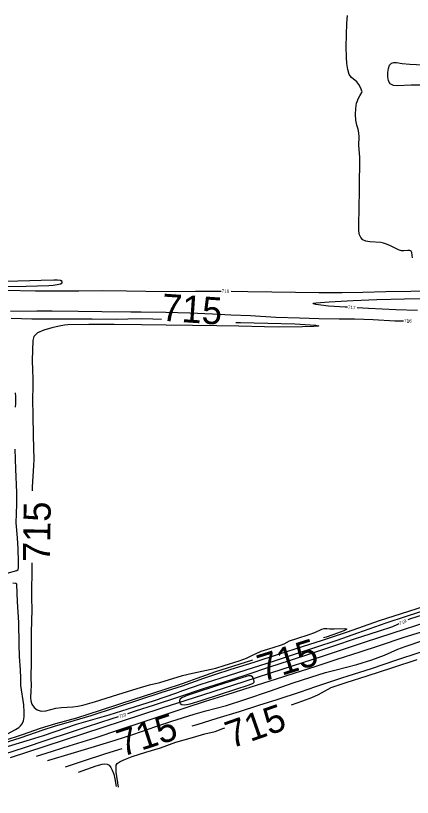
# Model space of a CAD drawing. Extents: x -468563856 to 36492962, y -306094093 to 11899197.
# Drawn here: x 1820050 to 1820533, y 530391 to 531343 of the extents above; entities that cross this region are included whole.
import ezdxf

# ---------------------------------------------------------------- set-up
doc = ezdxf.new("R2010")
doc.units = 0
for name, color, linetype in [('DT_X_Contour_Minor', 7, 'Continuous'), ('Level 14', 7, 'Continuous'), ('Level 19', 7, 'Continuous')]:
    doc.layers.add(name, color=color, linetype=linetype)

msp = doc.modelspace()

# ---------------------------------------------------------------- linework, layer by layer
at = {"layer": 'DT_X_Contour_Minor'}
for points in [[(1820466.33, 531239.8), (1820467.1, 531242.15), (1820469.18, 531245.91), (1820471.87, 531249.69), (1820471.98, 531250.79), (1820470.08, 531255.7), (1820468.15, 531259.47), (1820465.56, 531262.92), (1820459.18, 531267.98), (1820456.4, 531271.79), (1820454.53, 531277.77), (1820453.44, 531285.12), (1820452.87, 531292.66), (1820452.58, 531305.86), (1820452.86, 531319.49), (1820453.6, 531334.34), (1820454.38, 531343.39)], [(1820554.3, 531258.8), (1820531.6, 531258.86), (1820515.27, 531258.02), (1820510.24, 531258.39), (1820506.37, 531260.2), (1820504.16, 531263.92), (1820503.35, 531268.9), (1820503.48, 531274.25), (1820504.2, 531279.12), (1820505.55, 531283.02), (1820507.66, 531285.55), (1820510.58, 531286.46), (1820513.97, 531286.25), (1820520.75, 531285.01), (1820530.32, 531284.19), (1820554.56, 531283.23)], [(1820533.31, 531048.28), (1820532.58, 531054.96), (1820531.75, 531056.64), (1820530.07, 531057.29), (1820527.78, 531057.27), (1820522.81, 531056.83), (1820520.03, 531057.16), (1820516.43, 531058.3), (1820506.6, 531062.92), (1820501.83, 531065.14), (1820498, 531066.51), (1820494.61, 531067.16), (1820481.28, 531067.92), (1820476.67, 531068.81), (1820473.04, 531070.48), (1820470.45, 531073.06), (1820468.82, 531076.58), (1820468.04, 531081.03), (1820467.84, 531086.05), (1820468.39, 531111.42), (1820468.79, 531128.59), (1820468.97, 531144.22), (1820469.33, 531159.11), (1820469.04, 531170.5), (1820468.05, 531185.76), (1820468.36, 531195.83), (1820468.06, 531200.67), (1820467.01, 531205.3), (1820465.6, 531210.18), (1820464.41, 531215.91), (1820463.89, 531222.82), (1820464.17, 531230.15), (1820465.27, 531236.87), (1820466.33, 531239.8)], [(1819858.47, 531016.5), (1819874.25, 531016.03), (1819901.63, 531015.56), (1819930.13, 531015), (1819963.03, 531014.01), (1819983.8, 531013.7), (1820018.21, 531013.65), (1820033.98, 531013.43), (1820062.78, 531014.12), (1820090.66, 531014.82), (1820095.79, 531015.2), (1820100.88, 531015.85), (1820104.86, 531016.84), (1820106.85, 531018.19), (1820106.8, 531019.62), (1820104.83, 531020.75), (1820101.19, 531021.33), (1820096.45, 531021.45), (1820081.35, 531020.88), (1820067.45, 531020.45), (1820038.31, 531019.53), (1820029.69, 531019.43)], [(1819643.06, 531014.48), (1819666.9, 531014.02), (1819695.98, 531013.52), (1819721.13, 531013.2), (1819750.34, 531012.81), (1819784.04, 531012.39), (1819810.69, 531011.89), (1819838.93, 531011.3), (1819869.9, 531011.21), (1819907.1, 531010.74), (1819937.02, 531010.46), (1819972.82, 531010.14), (1820003.71, 531009.72), (1820037.35, 531009.26), (1820074.26, 531008.3), (1820093.49, 531008.12), (1820127.08, 531008.25), (1820155.77, 531008.64), (1820184.94, 531008.41), (1820208.61, 531007.92), (1820244.29, 531007.51), (1820269.27, 531007.68), (1820300.38, 531007.87)], [(1820312.38, 531007.74), (1820332.78, 531007.37), (1820362.21, 531006.96), (1820390.83, 531006.48), (1820419.24, 531006.26), (1820447.84, 531006.31), (1820473.03, 531006.54), (1820500.98, 531007.32), (1820531.19, 531007.79), (1820554.4, 531008.3)], [(1820454.05, 530988.41), (1820451.44, 530988.56), (1820431.13, 530989.76), (1820415.68, 530991.78), (1820412.63, 530992.4), (1820412.41, 530993.07), (1820416.2, 530993.75), (1820432.03, 530995.05), (1820460.99, 530996.51), (1820490.08, 530997.63), (1820523.7, 530998.33), (1820549.42, 530998.81)], [(1820043.94, 530983.51), (1820075.99, 530983.99), (1820094.66, 530984.05), (1820126.32, 530983.58), (1820155.05, 530983.13), (1820190.22, 530982.64), (1820203.03, 530982.87), (1820232.85, 530982.34), (1820262.3, 530981.56), (1820289.73, 530980.3), (1820312.09, 530978.99), (1820336.08, 530978.39), (1820367.11, 530976.37), (1820395.88, 530975.42), (1820419.48, 530974.78), (1820444.13, 530974.34), (1820462.94, 530974.06), (1820485.5, 530973.22), (1820511.86, 530971.77), (1820522.53, 530971.73)], [(1820539.43, 530984.19), (1820513.21, 530985.33), (1820479.62, 530986.93), (1820466.03, 530987.72)], [(1820044.52, 530975.05), (1820069.74, 530974.32), (1820084.28, 530974.13), (1820114.28, 530974.23), (1820143.33, 530974.12), (1820172.73, 530973.92), (1820186.8, 530974), (1820203.68, 530974.57), (1820217.01, 530974.16), (1820227.93, 530973.82)], [(1820318.43, 530969.89), (1820324.02, 530969.67), (1820357.17, 530968.78), (1820389.93, 530967.99), (1820396.72, 530967.78), (1820408.88, 530966.95), (1820415.48, 530966.3), (1820419.2, 530965.64), (1820418.17, 530965.09), (1820413.41, 530964.67), (1820399.27, 530964.26), (1820370.55, 530964.11), (1820353.32, 530964.33), (1820321.99, 530965.19), (1820295.17, 530965.67), (1820265.45, 530965.94), (1820233.53, 530966.29), (1820203.5, 530966.75), (1820170.08, 530967.25), (1820139.21, 530967.09), (1820113.68, 530966.81), (1820109.49, 530966.36), (1820103.06, 530965.26), (1820094.09, 530963.3), (1820084.48, 530960.5), (1820076.67, 530956.95), (1820072.45, 530952.76), (1820070.98, 530947.94), (1820070.26, 530923.79), (1820070.68, 530911.4), (1820071.14, 530901.56), (1820071.11, 530892.82), (1820070.63, 530875.01), (1820070.94, 530857.2), (1820071.3, 530831.7), (1820072.23, 530802.98), (1820072.03, 530795.68), (1820070.37, 530769.1), (1820070.26, 530764.75)], [(1820050.08, 530866.43), (1820050.46, 530870.63), (1820050.46, 530879.72), (1820050.11, 530884.08)], [(1820039.71, 530664.59), (1820051.51, 530667.67), (1820053.24, 530668.91), (1820053.62, 530670.84), (1820053.64, 530678.16), (1820053.21, 530694), (1820052.22, 530707.51), (1820050.58, 530725.96), (1820051.54, 530748.62), (1820051.5, 530762.64), (1820050.55, 530790.91), (1820049.53, 530815.45)], [(1820975, 530749.89), (1820974.39, 530749.69), (1820955.82, 530743.7), (1820926.89, 530734.79), (1820898.46, 530725.6), (1820872.39, 530717.07), (1820843.48, 530707.6), (1820815.52, 530698.58), (1820788.91, 530689.89), (1820759.92, 530680.44), (1820733.01, 530671.94), (1820706.96, 530663.61), (1820679.3, 530654.6), (1820651.55, 530645.41), (1820642.4, 530642.94), (1820632.42, 530641.65), (1820626.79, 530640.14), (1820605.78, 530633.36), (1820576.19, 530623.56), (1820546.48, 530613.85), (1820531, 530608.69), (1820527.63, 530607.45)], [(1820069.85, 530677.14), (1820070, 530673.23), (1820069.76, 530663.22), (1820069.24, 530646.18), (1820069.37, 530634.36), (1820069.8, 530619.63), (1820068.94, 530592.7), (1820068.87, 530567.51), (1820069.1, 530557.47), (1820068.61, 530536.58), (1820069.02, 530528.17), (1820068.67, 530520.75), (1820068.15, 530513.02), (1820068.5, 530508.93), (1820069.87, 530504.87), (1820072.6, 530501.08), (1820076.53, 530498.12), (1820081.31, 530496.62), (1820086.7, 530496.96), (1820099.12, 530499.93), (1820106.08, 530500.79), (1820119.82, 530501.63), (1820125.89, 530502.48), (1820131.85, 530503.82), (1820146.05, 530507.95), (1820174.76, 530516.68), (1820198.17, 530524.08), (1820212.95, 530528.32), (1820225.55, 530531.53), (1820253.4, 530539.82), (1820265.44, 530542.72), (1820293.72, 530548.93), (1820303.85, 530551.94), (1820322.28, 530557.8), (1820331.25, 530561.07), (1820337.8, 530564.03), (1820343.13, 530566.75), (1820349.13, 530569.41), (1820357.03, 530572.12), (1820372.65, 530576.89), (1820377, 530578.52), (1820383.67, 530581.88), (1820392.71, 530584.95), (1820407.56, 530589.78), (1820414.47, 530592.31), (1820423.01, 530596.2), (1820425.88, 530597.08), (1820428.87, 530597.11), (1820432.69, 530596.71), (1820438.02, 530596.48), (1820451, 530597), (1820453.29, 530596.37), (1820449.83, 530594.38), (1820436.21, 530589.26), (1820428.07, 530586.52), (1820425.07, 530585.59)], [(1820040.2, 530468.81), (1820050.15, 530474.11), (1820053.97, 530476.63), (1820056.02, 530478.38), (1820058, 530480.9), (1820059.52, 530484.58), (1820060.31, 530489.55), (1820060.49, 530495.06), (1820059.93, 530504.12), (1820056.64, 530527.55), (1820056.36, 530536.77), (1820055.97, 530546.62), (1820054.88, 530563), (1820054.54, 530578.08), (1820054.03, 530604.41), (1820052.28, 530629.38), (1820051.43, 530651.11), (1820050.18, 530651.82), (1820046.88, 530652.48)], [(1820739.43, 530632.78), (1820718.62, 530626.11), (1820701.76, 530620.43), (1820674.7, 530611.84), (1820659.02, 530606.82), (1820627.65, 530596.01), (1820609.42, 530589.65), (1820580.36, 530579.93), (1820572.52, 530577.51), (1820541.13, 530567.28), (1820513.91, 530558.43), (1820483.19, 530548.12), (1820454.82, 530539.23), (1820446.73, 530536.65), (1820415.19, 530525.87), (1820396.62, 530519.72), (1820368.26, 530510.3), (1820345.95, 530503.3), (1820322.25, 530495.81), (1820295.29, 530487.44), (1820270.81, 530479.96), (1820264.78, 530478.05)], [(1820547.68, 530624.01), (1820519.59, 530615.03), (1820492.74, 530606.26), (1820473.23, 530599.58), (1820453.65, 530592.62), (1820423.53, 530582.32), (1820399.03, 530574.64), (1820371, 530565.67), (1820340.36, 530555.79), (1820311.99, 530546.98), (1820292.09, 530540.8), (1820278.77, 530536.16), (1820253.04, 530526.96), (1820227.11, 530518.62), (1820200.89, 530510.08), (1820171.24, 530500.36), (1820141.58, 530490.7), (1820120.93, 530484.56), (1820097.09, 530477.71), (1820084.29, 530473.61), (1820055.03, 530463.63), (1820023.65, 530453.82)], [(1820035.98, 530452.21), (1820073.33, 530463.49), (1820083.87, 530466.96), (1820111.34, 530476.3), (1820124.26, 530480.39), (1820152.76, 530488.63), (1820163.98, 530491.81), (1820187.22, 530499.21), (1820219.08, 530509.55), (1820245.27, 530518.29), (1820253.76, 530521.67), (1820275.93, 530529.38), (1820299.09, 530536.64), (1820330.8, 530546.64), (1820364.03, 530557.42), (1820391.03, 530566.34), (1820414.28, 530573.87), (1820441.5, 530582.79), (1820466.76, 530591.9), (1820501.45, 530604.04), (1820526.16, 530612.23), (1820552.63, 530620.56)], [(1820075.51, 530441.43), (1820087.42, 530445.4), (1820115.34, 530454.39), (1820146.83, 530464.12), (1820177.17, 530473.97), (1820205.38, 530483.31), (1820232.14, 530492.46), (1820257.81, 530501.03), (1820281.44, 530508.58), (1820307.79, 530516.82), (1820336.91, 530525.99), (1820366.57, 530535.4), (1820389.44, 530542.78), (1820416.12, 530551.36), (1820441.62, 530559.58), (1820469.44, 530568.53), (1820493.22, 530576.28), (1820523.05, 530586.42), (1820542.91, 530592.65), (1820572.16, 530601.61), (1820581.7, 530604.81)], [(1820516.59, 530602.75), (1820515.14, 530602.09), (1820508.9, 530599.3), (1820491.69, 530593.62), (1820462.44, 530583.96), (1820438.2, 530575.84), (1820409.18, 530566.13), (1820384.33, 530557.96), (1820358.04, 530549.4), (1820331.71, 530540.81), (1820301.66, 530530.98), (1820277.33, 530523.08), (1820248.36, 530513.65), (1820217.47, 530503.38), (1820197.08, 530496.63), (1820186.48, 530493.18)], [(1820089.02, 530436.34), (1820090.52, 530436.81), (1820117.62, 530444.67), (1820142.09, 530452.12), (1820171.19, 530461.12), (1820192.97, 530468.15), (1820221.02, 530477.77), (1820240.51, 530484.21), (1820267.67, 530492.78), (1820281.61, 530496.65), (1820306.77, 530503.32), (1820329.04, 530510.66), (1820360.26, 530521.18), (1820386.97, 530530.45), (1820409.47, 530537.72), (1820427.5, 530543.42), (1820440.44, 530546.79), (1820465.59, 530553.3), (1820483.73, 530558.82), (1820491.63, 530561.61), (1820499.12, 530564.69), (1820515.54, 530572.04), (1820524.27, 530575.19), (1820547.11, 530582.88)], [(1820338.6, 530558.33), (1820321.94, 530553.17), (1820293.38, 530544.36), (1820270.69, 530536.04), (1820252.92, 530529.64), (1820230.39, 530522.49), (1820206.59, 530514.86), (1820178, 530505.51), (1820153.03, 530497.31), (1820124.29, 530488.06), (1820098.86, 530480.92), (1820080.14, 530475.45), (1820057.92, 530467.7), (1820035.86, 530460.29), (1820018.33, 530454.81), (1819993.18, 530447.62), (1819959.63, 530438.56), (1819932.76, 530430.1), (1819912.01, 530423.44), (1819885.79, 530414.17), (1819864.83, 530406.97), (1819837.4, 530398.39), (1819816.27, 530391.63), (1819815.75, 530391.46)], [(1820385.87, 530504.21), (1820399.9, 530509.01), (1820410.84, 530513.12), (1820418.79, 530516.89), (1820434.2, 530525.21), (1820452.74, 530531.49), (1820478.23, 530539.43), (1820509.49, 530549.57), (1820539.19, 530559.14)], [(1820325.68, 530537.16), (1820295.82, 530527.51), (1820266.18, 530517.91), (1820259.13, 530515.42), (1820253.28, 530512.93), (1820250.24, 530510.84), (1820249.46, 530509.04), (1820249.82, 530507.32), (1820250.57, 530505.62), (1820252.35, 530504.38), (1820256.15, 530504.21), (1820262.46, 530505.46), (1820275.92, 530509.42), (1820299.48, 530517), (1820334.47, 530528.37), (1820339.47, 530530.53), (1820340.58, 530531.57), (1820340.74, 530532.72), (1820339.62, 530536.14), (1820338.46, 530538.03), (1820336.58, 530539.25), (1820333.87, 530539.39), (1820330.9, 530538.8), (1820325.68, 530537.16)], [(1820355.26, 530494.81), (1820355.7, 530494.96)], [(1820175.07, 530489.47), (1820167.23, 530486.93), (1820137.27, 530477.4), (1820116.57, 530470.61), (1820088.23, 530461.01), (1820060.51, 530451.95), (1820036.58, 530444.21)], [(1820175.23, 530403.88), (1820172.68, 530422.1), (1820172.45, 530428.84), (1820172.57, 530430.86), (1820173.81, 530432.85), (1820177.31, 530435.16), (1820183.76, 530438.03), (1820192.08, 530441.15), (1820208.48, 530446.5), (1820226.45, 530451.88), (1820245.03, 530458.66), (1820265.61, 530464.33), (1820280.45, 530468.73), (1820293.26, 530471.75), (1820302.44, 530475.39), (1820304.77, 530476.32)], [(1820179.38, 530450.48), (1820159.63, 530444.29), (1820131, 530435.06), (1820110.38, 530428.3)], [(1820126.87, 530422.09), (1820136.89, 530425.66), (1820148.26, 530429.93), (1820155.68, 530431.88), (1820158.92, 530432.31), (1820161.75, 530432.01), (1820164.16, 530430.61), (1820166.17, 530427.95), (1820167.75, 530424.72), (1820169.6, 530419.76), (1820170.92, 530413.93), (1820172.73, 530404.82)]]:
    msp.add_lwpolyline(points, dxfattribs=at)
at = {"layer": 'Level 14'}
msp.add_lwpolyline([(1820574.95, 530612.67), (1820524.52, 530596.36), (1820475.9, 530580.55), (1820423.25, 530563.09), (1820375.32, 530547.63), (1820327.83, 530532.02), (1820278.94, 530516.23), (1820226.77, 530499.51), (1820179.84, 530484.06), (1820132.77, 530468.67), (1820085.62, 530453.49), (1820043.35, 530439.51)], dxfattribs=at)

# ---------------------------------------------------------------- texts
at = {"layer": 'Level 19'}
for s, height, rotation, p in [('716', 4, 358.97525, (1820300.99, 531005.94)), ('715', 33, 356.0417, (1820227.04, 530972.02)), ('717', 4, 356.67769, (1820454.67, 530986.37)), ('716', 4, 359.77739, (1820523.17, 530969.72)), ('715', 33, 89.24964, (1820091.98, 530677.85)), ('719', 4, 24.21893, (1820518.09, 530601.23)), ('715', 33, 17.42938, (1820350.75, 530532.03)), ('715', 33, 19.25138, (1820312.5, 530450.7)), ('719', 4, 18.00806, (1820176.39, 530487.8)), ('715', 33, 18.02525, (1820179.8, 530440.63))]:
    msp.add_text(s, height=height, rotation=rotation, dxfattribs=at).set_placement(p)

doc.saveas('drawing.dxf')
